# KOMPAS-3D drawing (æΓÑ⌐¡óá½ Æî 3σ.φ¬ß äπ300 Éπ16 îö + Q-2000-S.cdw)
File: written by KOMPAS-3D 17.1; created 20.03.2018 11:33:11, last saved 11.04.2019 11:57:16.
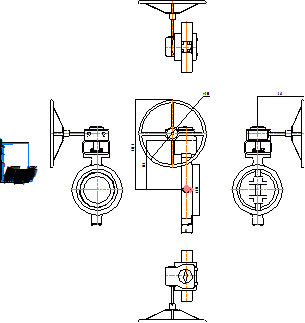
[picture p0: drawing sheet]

Sheet 1: A4, portrait

Title block, sheet 1: name: Стейнвал ТМ 3х.экс / Ду300 Ру16 МФ + Q-2000-S; material: Внимание! Данный продукт является объектом авторского права ООО «Торговый Дом АДЛ». / Запрещается изменение, копирование, распространение / (в том числе путем копирования на другие сайты и ресурсы в Интернете) / или любое иное использование информации и объектов без предварительного / согласия правообладателя (ООО «Торговый Дом АДЛ»).; mass: 97,3; sheets: 1; organisation: ООО "Торговый дом АДЛ"; sheet format: A4; stored path: \\adlc.lan\data\АДЛ_ПКД\3D-модели\ADL production\Дисковые поворотные затворы СТЕЙНВАЛ\Трехэксцентриковый\Стейнвал м-ф\С редуктором\KOMPAS 2D\Стейнвал ТМ 3х.экс Ду300 Ру16 МФ + Q-2000-S.cdw

Views: Вид 1, Проекционный вид 2, Проекционный вид 4, Проекционный вид 5
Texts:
  kka
  adl
Dimensions and other numbers on the sheet: 365; 664,5; 83; 375; 500; 345; 1:1; 1; 97,3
